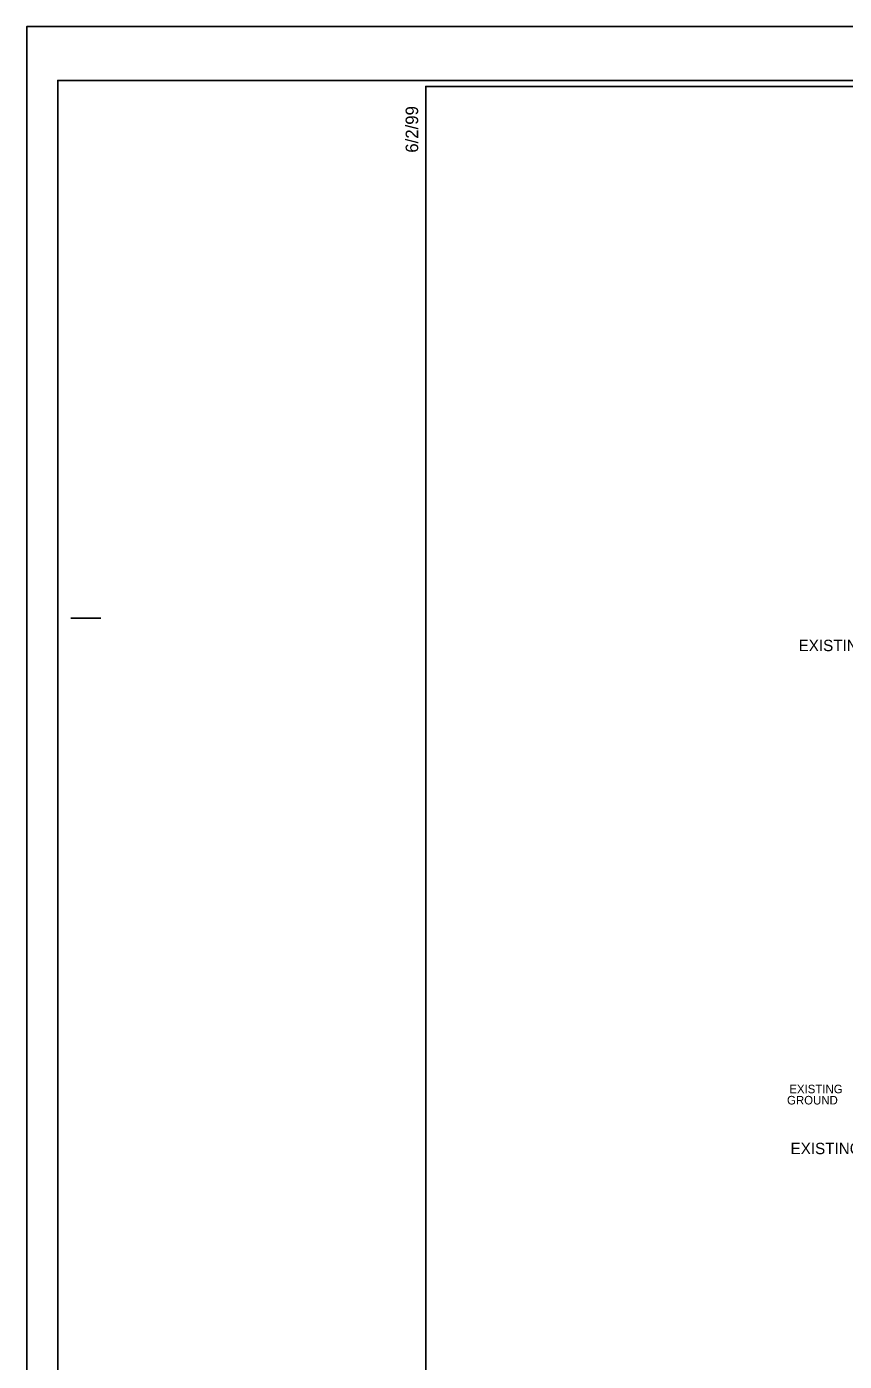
# Model space of a CAD drawing. Extents: x 1022283 to 1026986, y 174822 to 180471.
# Drawn here: x 1022283 to 1023139, y 176176 to 177572 of the extents above; entities that cross this region are included whole.
import ezdxf

# ---------------------------------------------------------------- set-up
doc = ezdxf.new("R2010")
doc.units = 0
for name, color, linetype in [('Sheet Cutting Line CELL', 7, 'Continuous'), ('Sheet Plot Border Inside CELL', 7, 'Continuous'), ('Sheet Plot Border Outside CELL', 7, 'Continuous'), ('Sheet Typical CELL', 7, 'Continuous'), ('Typical Slope Point Local CELL', 7, 'Continuous'), ('Typical Text General CELL', 7, 'Continuous')]:
    doc.layers.add(name, color=color, linetype=linetype)

msp = doc.modelspace()

# ---------------------------------------------------------------- linework, layer by layer
at = {"layer": 'Sheet Cutting Line CELL'}
for p, q in [((1026493.2, 177572.5), (1022283.2, 177572.5)), ((1022283.2, 177572.5), (1022283.2, 174822.5))]:
    msp.add_line(p, q, dxfattribs=at)
at = {"layer": 'Sheet Plot Border Inside CELL'}
msp.add_lwpolyline([(1026482, 177516.3), (1022315.7, 177516.3), (1022315.7, 174878.6), (1026482, 174878.6)], close=True, dxfattribs=at)
at = {"layer": 'Sheet Plot Border Outside CELL'}
msp.add_lwpolyline([(1026493.2, 177572.5), (1022283.2, 177572.5), (1022283.2, 174822.5), (1026493.2, 174822.5)], close=True, dxfattribs=at)
at = {"layer": 'Sheet Typical CELL'}
msp.add_line((1022329.5, 176953.7), (1022360.7, 176953.7), dxfattribs=at)
msp.add_lwpolyline([(1026450.7, 177510), (1022700.7, 177510), (1022700.7, 174885), (1026450.7, 174885)], close=True, dxfattribs=at)

# ---------------------------------------------------------------- texts
msp.add_text('6/2/99', height=13.12, rotation=90, dxfattribs=at).set_placement((1022692.8, 177440.6))
at = {"layer": 'Typical Slope Point Local CELL'}
for s, p in [('EXISTING ', (1023081.1, 176456.5)), ('EXISTING ', (1023081.1, 176456.5)), ('GROUND', (1023078.7, 176444.8)), ('GROUND', (1023078.7, 176444.8))]:
    msp.add_text(s, height=8.94, dxfattribs=at).set_placement(p)
at = {"layer": 'Typical Text General CELL'}
for p in [(1023090.8, 176919.1), (1023082.4, 176392.8)]:
    msp.add_text('EXISTING SIDEWALK', height=11.898, dxfattribs=at).set_placement(p)

doc.saveas('drawing.dxf')
